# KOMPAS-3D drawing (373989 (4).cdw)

Referenced files in C:\Documents and Settings\оля\Мои документы\Чертежи схемы установок\: На внутреннюю цилиндрическую поверхность.frw, На плоскости.frw, Направление усилия.frw
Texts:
  Текст на чертеже
  Размерные надписи
  Шероховатость
  Линия-выноска #1
  Линия-выноска #2
  Линия-выноска #3
  Отклонения формы и база
  Заголовок таблицы
  Ячейка таблицы
  Стрелка вида
  Обозначение изменения
  Фигурная скобка
  Номер узла
  Марка координационной оси
  VRCB
  Выносная надпись
  Обозначение узла
  Марка/позиционное обозначение с линией-выноской
  Марка/позиционное обозначение на линии
  Марка/позиционное обозначение без линии-выноски
  Упор
  Оля
  Изм. Лист № докум      Подпись      Дата
  Дублик
  Взамен
  Подпись
  Изм.
  Лист
  № докумен.
  Дата
  ТС-51.60240
  СК-4.54.60640
  Операция 10. Протяжная
  Ra3.2
  Операция 15. Токарная
  Ra2.5
  Rz 20
Dimensions and other numbers on the sheet: 7; 71,385; 2; 114,8; 2 фаски; 1:1; 1; 3; 4; 5; 6; 8; 9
